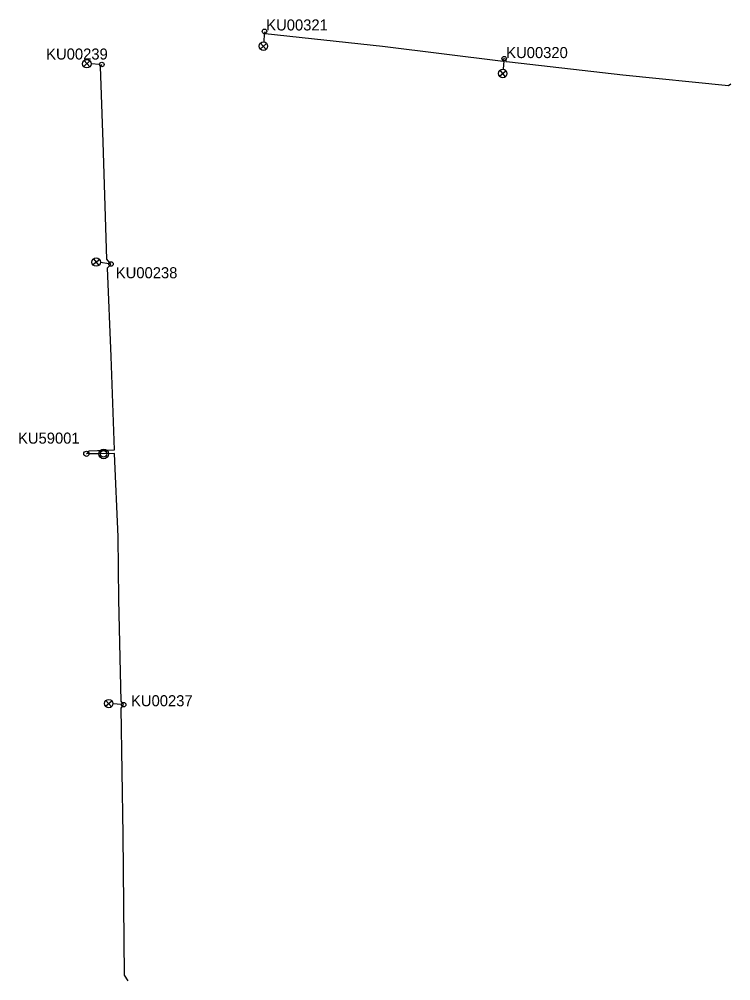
# Model space of a CAD drawing. Extents: x -727792 to -727658, y -1063536 to -1063043.
# Drawn here: x -727762 to -727665.4, y -1063536 to -1063405.4 of the extents above; entities that cross this region are included whole.
import ezdxf

# ---------------------------------------------------------------- set-up
doc = ezdxf.new("R2010")
doc.units = 0
for name, color, linetype in [('Kabelove_vedeni_zemni', 7, 'Continuous'), ('Prisvetleni_prechodu', 7, 'Continuous'), ('Prisvetleni_prechodu_popis', 7, 'Continuous'), ('Verejne_osvetleni', 7, 'Continuous'), ('Verejne_osvetleni_popis', 7, 'Continuous')]:
    doc.layers.add(name, color=color, linetype=linetype)

msp = doc.modelspace()

# ---------------------------------------------------------------- linework, layer by layer
at = {"layer": 'Kabelove_vedeni_zemni'}
for points in [[(-727728.68, -1063407.06), (-727728.6, -1063407.36), (-727712.63, -1063409.05), (-727696.28, -1063411.1), (-727696.31, -1063410.88), (-727696.12, -1063410.76)], [(-727749.53, -1063438.66), (-727750.07, -1063438.02), (-727750.59, -1063422.09), (-727750.96, -1063411.85), (-727750.78, -1063411.56)], [(-727696.12, -1063410.76), (-727695.91, -1063410.86), (-727695.88, -1063411.15), (-727695.41, -1063411.21), (-727680, -1063412.98), (-727665.65, -1063414.43), (-727665.35, -1063414.19)], [(-727752.87, -1063464.42), (-727752.49, -1063464.01), (-727749.07, -1063463.89), (-727749.5, -1063451.23), (-727750, -1063439.17), (-727749.53, -1063438.66)], [(-727747.81, -1063498.49), (-727748.13, -1063498), (-727748.44, -1063484.21), (-727748.56, -1063475.69), (-727749.06, -1063464.37), (-727752.87, -1063464.42)], [(-727747.2, -1063535.99), (-727747.67, -1063535.25), (-727747.87, -1063516.17), (-727748.15, -1063498.98), (-727747.81, -1063498.49)]]:
    msp.add_lwpolyline(points, dxfattribs=at)
at = {"layer": 'Prisvetleni_prechodu'}
msp.add_line((-727751.19, -1063464.44), (-727752.52, -1063464.42), dxfattribs=at)
for centre, radius in [((-727750.53, -1063464.44), 0.662), ((-727752.87, -1063464.42), 0.353), ((-727750.53, -1063464.44), 0.441)]:
    msp.add_circle(centre, radius, dxfattribs=at)
at = {"layer": 'Verejne_osvetleni'}
for p, q in [((-727728.7, -1063407.37), (-727728.78, -1063408.51)), ((-727729.26, -1063409.46), (-727728.39, -1063408.71)), ((-727728.45, -1063409.51), (-727729.2, -1063408.65)), ((-727753.23, -1063411.85), (-727752.38, -1063411.08)), ((-727753.19, -1063411.04), (-727752.42, -1063411.89)), ((-727751.09, -1063411.54), (-727752.23, -1063411.49)), ((-727696.15, -1063411.06), (-727696.27, -1063412.21)), ((-727696.77, -1063413.14), (-727695.88, -1063412.41)), ((-727695.96, -1063413.22), (-727696.69, -1063412.33)), ((-727751.99, -1063438.74), (-727751.08, -1063438.04)), ((-727751.89, -1063437.93), (-727751.19, -1063438.84)), ((-727749.83, -1063438.62), (-727750.97, -1063438.46)), ((-727750.21, -1063497.91), (-727749.46, -1063498.78)), ((-727750.26, -1063498.72), (-727749.4, -1063497.97)), ((-727748.12, -1063498.47), (-727749.26, -1063498.39))]:
    msp.add_line(p, q, dxfattribs=at)
for centre, radius in [((-727728.68, -1063407.06), 0.306), ((-727728.83, -1063409.08), 0.574), ((-727752.8, -1063411.46), 0.574), ((-727750.78, -1063411.56), 0.306), ((-727696.12, -1063410.76), 0.306), ((-727696.32, -1063412.78), 0.574), ((-727751.54, -1063438.39), 0.574), ((-727749.53, -1063438.66), 0.306), ((-727749.83, -1063498.35), 0.574), ((-727747.81, -1063498.49), 0.306)]:
    msp.add_circle(centre, radius, dxfattribs=at)

# ---------------------------------------------------------------- texts
at = {"layer": 'Prisvetleni_prechodu_popis'}
msp.add_text('KU59001', height=1.5, dxfattribs=at).set_placement((-727762.15, -1063463.05))
at = {"layer": 'Verejne_osvetleni_popis'}
for s, p in [('KU00321', (-727728.44, -1063406.94)), ('KU00239', (-727758.33, -1063410.89)), ('KU00320', (-727695.85, -1063410.69)), ('KU00238', (-727748.87, -1063440.59)), ('KU00237', (-727746.8, -1063498.71))]:
    msp.add_text(s, height=1.5, dxfattribs=at).set_placement(p)

doc.saveas('drawing.dxf')
